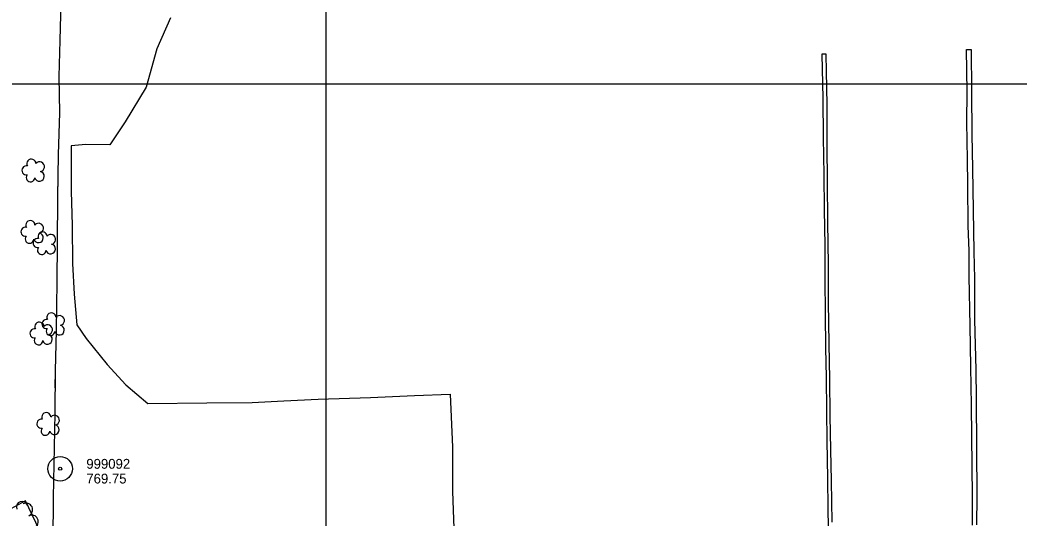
# Model space of a CAD drawing. Extents: x 591954 to 597000, y 198576 to 213500.
# Drawn here: x 592813 to 593423, y 204235 to 204539 of the extents above; entities that cross this region are included whole.
import ezdxf

# ---------------------------------------------------------------- set-up
doc = ezdxf.new("R2010")
doc.units = 0
for name, color, linetype in [('Level 10', 7, 'Continuous'), ('Level 15', 7, 'Continuous'), ('Level 17', 7, 'Continuous'), ('Level 18', 7, 'Continuous'), ('Level 6', 7, 'Continuous')]:
    doc.layers.add(name, color=color, linetype=linetype)

msp = doc.modelspace()

# ---------------------------------------------------------------- linework, layer by layer
at = {"layer": 'Level 10'}
for p, q in [((593000, 204500), (593000, 206000)), ((593000, 203500), (593000, 205000)), ((592000, 204500), (594000, 204500)), ((592000, 204500), (594000, 204500)), ((593000, 204500), (595500, 204500)), ((593000, 203000), (593000, 204500))]:
    msp.add_line(p, q, dxfattribs=at)
at = {"layer": 'Level 15'}
for points in [[(592833.36, 204221.01), (592833.44, 204247.55), (592834.04, 204278.1), (592834.45, 204299.22), (592834.74, 204325.15), (592835.27, 204349.39), (592835.79, 204379.37), (592835.96, 204402.84), (592836.17, 204430.62), (592836.58, 204456.99), (592837.33, 204482.29), (592836.93, 204504.57), (592837.6, 204526.56), (592838.46, 204557.74), (592839.25, 204588.08), (592839.84, 204615.33), (592840.55, 204644.29), (592840.58, 204652.15), (592916.98, 204651.67), (592957.36, 204650.29), (592995.79, 204650.5), (593019.24, 204649.49), (593019.8, 204649.48)], [(592836.13, 204426.04), (592836.17, 204430.62), (592836.27, 204437.36)], [(592834.62, 204314.61), (592834.74, 204325.15), (592834.75, 204325.93)]]:
    msp.add_lwpolyline(points, dxfattribs=at)
at = {"layer": 'Level 17'}
for points in [[(592904.95, 204540.41), (592896.6, 204521.43), (592890.12, 204498.09), (592877.23, 204476.91), (592867.86, 204462.75), (592853.32, 204463.06), (592844.28, 204462.26), (592844.41, 204434.56), (592844.83, 204413.56), (592845.04, 204390.32), (592846.22, 204371.64), (592847.86, 204352.97), (592853.41, 204344.62), (592866.36, 204328.71), (592877.77, 204316.42), (592891.12, 204304.94), (592927.13, 204305.27), (592954.91, 204305.62), (592974.19, 204306.66), (592995.19, 204307.51), (593027.2, 204308.65), (593053.94, 204309.82), (593075.77, 204310.67), (593077.22, 204278.31), (593077.31, 204251.18), (593078.38, 204217.39)], [(593302.79, 204518.17), (593303.32, 204491.19), (593303.56, 204467.35), (593303.92, 204444.43), (593304.14, 204423.28), (593304.61, 204401.26), (593304.6, 204380.81), (593304.91, 204359.77), (593305.05, 204338.82), (593305.43, 204321.13), (593305.66, 204300.28), (593305.89, 204282.29), (593306.26, 204259.27), (593306.35, 204240.98), (593306.78, 204217.79)], [(593309.04, 204232.56), (593308.62, 204257.75), (593308.28, 204276.72), (593307.92, 204297.39), (593307.72, 204319.82), (593307.26, 204341.46), (593306.92, 204366.81), (593306.77, 204389.81), (593306.44, 204415.37), (593306.22, 204440.56), (593306.01, 204462.05), (593305.98, 204487.54), (593305.59, 204507.51), (593305.44, 204518.1), (593302.79, 204518.17)], [(593394.79, 204230.62), (593394.75, 204248.19), (593394.1, 204303.75), (593393.83, 204327.36), (593393.27, 204352.46), (593392.82, 204382.51), (593392.74, 204398.19), (593392.24, 204413.35), (593392, 204438.55), (593391.74, 204453.98), (593391.33, 204476.75), (593391.45, 204495.13), (593391.2, 204521.07), (593394.05, 204520.95), (593394.25, 204495.48), (593394.44, 204469.12), (593394.77, 204448.32), (593395.19, 204422.91), (593395.65, 204397.6), (593395.93, 204381.32), (593396.08, 204356.09), (593396.77, 204325.52), (593396.95, 204307.86), (593397.49, 204248.15), (593397.3, 204231)]]:
    msp.add_lwpolyline(points, dxfattribs=at)
at = {"layer": 'Level 18'}
msp.add_lwpolyline([(592756.31, 204014.27), (592768.98, 204022.22), (592791.78, 204038.52), (592799.71, 204066.61), (592803.03, 204121.2), (592817.15, 204131.41), (592826.86, 204147.44), (592828.71, 204190.81), (592824.8, 204228.11), (592816.49, 204245.61), (592805.3, 204239.41), (592797.34, 204205.11), (592783.3, 204163.07), (592781.03, 204152.49), (592747.45, 204164.07), (592750.56, 204200.5), (592756.46, 204239.96), (592750.18, 204278.32), (592746.12, 204303.09), (592738.44, 204312.57), (592736.09, 204313.03)], dxfattribs=at)
for centre, radius, start, end in [((592820.01, 204451.32), 2.78, 1.39455, 209.16754), ((592817.01, 204447.24), 2.78, 78.07156, 279.08261), ((592825.05, 204449.46), 2.97, 278.42366, 139.65754), ((592819.47, 204442.85), 2.61, 140.77971, 358.71232), ((592824.94, 204443.61), 2.97, 196.07448, 79.04774), ((592816.41, 204409.76), 2.78, 78.07156, 279.08261), ((592819.41, 204413.83), 2.78, 1.39455, 209.16754), ((592824.46, 204411.98), 2.97, 278.42366, 139.65754), ((592818.88, 204405.36), 2.61, 140.77971, 358.71232), ((592823.84, 204402.89), 2.78, 78.07156, 279.08261), ((592824.34, 204406.12), 2.97, 196.07448, 79.04774), ((592826.84, 204406.97), 2.78, 1.39455, 209.16754), ((592831.88, 204405.11), 2.97, 278.42366, 139.65754), ((592826.3, 204398.49), 2.61, 140.77971, 358.71232), ((592831.77, 204399.26), 2.97, 196.07448, 79.04774), ((592832.23, 204357.5), 2.78, 1.39455, 209.16754), ((592837.27, 204355.64), 2.97, 278.42366, 139.65754), ((592821.9, 204347.77), 2.78, 78.07156, 279.08261), ((592824.9, 204351.85), 2.78, 1.39455, 209.16754), ((592829.23, 204353.42), 2.78, 78.07156, 279.08261), ((592829.94, 204349.99), 2.97, 278.42366, 139.65754), ((592831.69, 204349.02), 2.61, 140.77971, 358.71232), ((592837.16, 204349.79), 2.97, 196.07448, 79.04774), ((592824.36, 204343.37), 2.61, 140.77971, 358.71232), ((592829.83, 204344.14), 2.97, 196.07448, 79.04774), ((592829.13, 204296.66), 2.78, 1.39455, 209.16754), ((592834.17, 204294.8), 2.97, 278.42366, 139.65754), ((592826.13, 204292.58), 2.78, 78.07156, 279.08261), ((592828.59, 204288.18), 2.61, 140.77971, 358.71232), ((592834.06, 204288.95), 2.97, 196.07448, 79.04774), ((592814.33, 204241.74), 3.45, 19.82496, 199.80963), ((592816.79, 204240.11), 4, 295.40874, 115.39342), ((592820.22, 204232.89), 4, 295.40874, 115.39342)]:
    msp.add_arc(centre, radius, start, end, dxfattribs=at)
at = {"layer": 'Level 6'}
for radius in [7.5, 7.5, 0.96, 0.96]:
    msp.add_circle((592837.59, 204265.14), radius, dxfattribs=at)

# ---------------------------------------------------------------- texts
for s, p in [('999092', (592853.58, 204265.14)), ('999092', (592853.58, 204265.14)), ('769.75', (592853.58, 204256.14)), ('769.75', (592853.58, 204256.14))]:
    msp.add_text(s, height=6, dxfattribs=at).set_placement(p)

doc.saveas('drawing.dxf')
